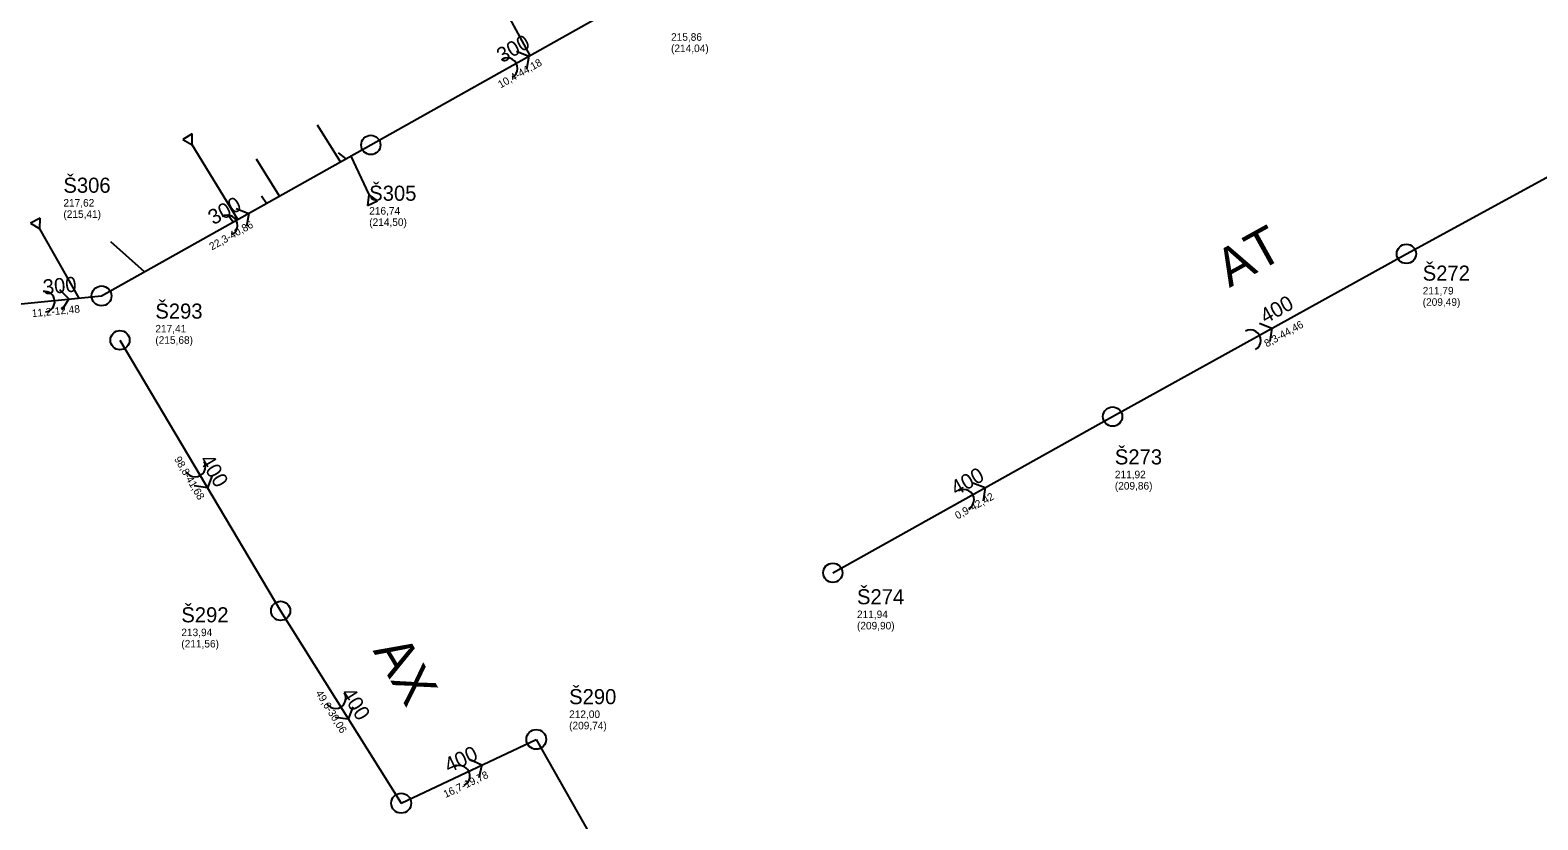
# Model space of a CAD drawing. Extents: x -574467 to -573663, y -1191209 to -1190406.
# Drawn here: x -574172.6 to -573973, y -1190649.1 to -1190544.6 of the extents above; entities that cross this region are included whole.
import ezdxf

# ---------------------------------------------------------------- set-up
doc = ezdxf.new("R2010")
doc.units = 0
for name, color, linetype in [('Vrstva 1', 7, 'Continuous'), ('Vrstva 12', 7, 'Continuous'), ('Vrstva 15', 7, 'Continuous'), ('Vrstva 29', 7, 'Continuous'), ('Vrstva 35', 7, 'Continuous'), ('Vrstva 41', 7, 'Continuous'), ('Vrstva 44', 7, 'Continuous'), ('Vrstva 45', 7, 'Continuous'), ('Vrstva 56', 7, 'Continuous'), ('Vrstva 57', 7, 'Continuous')]:
    doc.layers.add(name, color=color, linetype=linetype)

# ---------------------------------------------------------------- blocks, each defined once
blk = doc.blocks.new('100')
at = {"layer": 'Vrstva 1'}
blk.add_circle((0, 0), 1.27, dxfattribs=at)
blk = doc.blocks.new('106')
at = {"layer": 'Vrstva 1'}
for p, q in [((1.25, 0.72), (0, 0)), ((0, 0), (1.25, -0.72)), ((1.25, -0.72), (1.25, 0.72))]:
    blk.add_line(p, q, dxfattribs=at)
blk = doc.blocks.new('91')
at = {"layer": 'Vrstva 1'}
blk.add_lwpolyline([(0.79, 1.37), (1.89, 0), (0.79, -1.38)], dxfattribs=at)
blk.add_arc((-1.37, 0), 1.37, 270, 90, dxfattribs=at)
blk = doc.blocks.new('86')
at = {"layer": 'Vrstva 1'}
blk.add_lwpolyline([(0.79, 1.37), (1.89, 0), (0.79, -1.38)], dxfattribs=at)
blk.add_arc((-1.37, 0), 1.37, 270, 90, dxfattribs=at)

msp = doc.modelspace()

# ---------------------------------------------------------------- linework, layer by layer
at = {"layer": 'Vrstva 12'}
for p, q in [((-574106.44, -1190547.919), (-574112.039, -1190537.511)), ((-574131.516, -1190562.017), (-574134.55, -1190557.168)), ((-574145.096, -1190569.634), (-574151.152, -1190559.739)), ((-574130.766, -1190561.596), (-574131.785, -1190560.82)), ((-574139.584, -1190566.542), (-574142.65, -1190561.64)), ((-574130.164, -1190561.259), (-574127.779, -1190566.332)), ((-574141.319, -1190567.516), (-574141.976, -1190566.531)), ((-574145.75, -1190570.001), (-574146.416, -1190569.003)), ((-574166.126, -1190580.052), (-574171.298, -1190570.889)), ((-574157.463, -1190576.57), (-574161.921, -1190572.616))]:
    msp.add_line(p, q, dxfattribs=at)
at = {"layer": 'Vrstva 15'}
for p, q in [((-574127.51, -1190559.77), (-574089, -1190538.11)), ((-573990.44, -1190574.19), (-573950.17, -1190552.21)), ((-574163.15, -1190579.76), (-574127.51, -1190559.77)), ((-574029.33, -1190595.74), (-573990.44, -1190574.19)), ((-574175.57, -1190580.98), (-574163.15, -1190579.76)), ((-574160.71, -1190585.62), (-574139.45, -1190621.47)), ((-574066.36, -1190616.43), (-574029.33, -1190595.74)), ((-574139.45, -1190621.47), (-574123.49, -1190646.94)), ((-574123.49, -1190646.94), (-574105.61, -1190638.49)), ((-574105.61, -1190638.49), (-574090.06, -1190666.02))]:
    msp.add_line(p, q, dxfattribs=at)

# ---------------------------------------------------------------- block references
at = {"layer": 'Vrstva 12'}
for p, xscale, yscale, rotation in [((-574151.152, -1190559.739), 0.9999999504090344, 0.9999999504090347, 121.00000158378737), ((-574127.779, -1190566.332), 0.9999999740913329, 0.9999999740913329, -65.99999939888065), ((-574171.298, -1190570.889), 0.999999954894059, 0.9999999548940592, 119.00000058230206)]:
    msp.add_blockref('106', p, dxfattribs=dict(at, xscale=xscale, yscale=yscale, rotation=rotation))
at = {"layer": 'Vrstva 29'}
for p, xscale, yscale, rotation in [((-574127.51, -1190559.77), 1.0072562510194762, 1.0072562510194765, -151.23333635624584), ((-573990.44, -1190574.19), 1.0072562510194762, 1.0072562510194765, -151.23333635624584), ((-574163.15, -1190579.76), 1.0365458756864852, 1.0365458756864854, -158.02850914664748), ((-574160.71, -1190585.62), 0.9999999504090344, 0.9999999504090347, 121.00000158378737), ((-574029.33, -1190595.74), 1.0072562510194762, 1.0072562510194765, -151.23333635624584), ((-574066.36, -1190616.43), 1.0072562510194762, 1.0072562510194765, -151.23333635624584), ((-574139.45, -1190621.47), 0.9999999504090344, 0.9999999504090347, 121.00000158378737), ((-574105.61, -1190638.49), 1.0335064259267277, 1.033506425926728, 156.95871849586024), ((-574123.49, -1190646.94), 1.0365458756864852, 1.0365458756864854, 158.02850914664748)]:
    msp.add_blockref('100', p, dxfattribs=dict(at, xscale=xscale, yscale=yscale, rotation=rotation))
at = {"layer": 'Vrstva 41'}
for name, p, xscale, yscale, rotation in [('91', (-574108.255, -1190548.94), 1.0037041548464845, 1.0037041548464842, 29.379208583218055), ('91', (-574145.33, -1190569.765), 1.0037041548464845, 1.0037041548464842, 29.379208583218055), ('91', (-574169.36, -1190580.37), 1.0011216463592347, 1.0011216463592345, 6.5826102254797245), ('86', (-574009.885, -1190584.965), 1.0037041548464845, 1.0037041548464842, 29.379208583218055), ('86', (-574150.08, -1190603.545), 0.9999999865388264, 0.9999999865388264, -59.99999955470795), ('86', (-574047.845, -1190606.085), 1.0037041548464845, 1.0037041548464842, 29.379208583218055), ('86', (-574131.47, -1190634.205), 0.9999999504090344, 0.9999999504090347, -58.99999841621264), ('86', (-574114.55, -1190642.715), 1.0169561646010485, 1.0169561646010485, 26.97601647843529)]:
    msp.add_blockref(name, p, dxfattribs=dict(at, xscale=xscale, yscale=yscale, rotation=rotation))

# ---------------------------------------------------------------- texts
at = {"layer": 'Vrstva 35'}
for s, rotation, p in [('AT', 28.99, (-574013.868, -1190578.721)), ('AX', 300.67, (-574127.296, -1190626.74))]:
    msp.add_text(s, height=5, rotation=rotation, dxfattribs=at).set_placement(p)
at = {"layer": 'Vrstva 44'}
for s, rotation, p in [('300', 29.36, (-574110.138, -1190548.96)), ('300', 29.29, (-574148.341, -1190570.421)), ('300', 5.61, (-574170.819, -1190579.606)), ('400', 28.99, (-574009.086, -1190583.491)), ('400', 300.67, (-574150.251, -1190601.486)), ('400', 29.19, (-574050.03, -1190606.273)), ('400', 302.07, (-574131.537, -1190632.402)), ('400', 25.3, (-574117.183, -1190642.968))]:
    msp.add_text(s, height=2, rotation=rotation, dxfattribs=at).set_placement(p)
at = {"layer": 'Vrstva 45'}
for s, rotation, p in [('10,4-44,18', 29.36, (-574110.332, -1190552.287)), ('22,3-40,86', 29.29, (-574148.548, -1190573.747)), ('11,2-12,48', 5.61, (-574172.334, -1190582.575)), ('8,3-44,46', 28.99, (-574008.911, -1190586.595)), ('98,8-41,68', 300.67, (-574153.575, -1190601.374)), ('0,9-42,42', 29.19, (-574049.848, -1190609.378)), ('49,6-30,06', 302.07, (-574134.859, -1190632.366)), ('16,7-19,78', 25.3, (-574117.617, -1190646.264))]:
    msp.add_text(s, height=1, rotation=rotation, dxfattribs=at).set_placement(p)
at = {"layer": 'Vrstva 56'}
for s, p in [('215,86 ', (-574087.77, -1190545.97)), ('(214,04)', (-574087.77, -1190547.47)), ('217,62 ', (-574168.2, -1190567.93)), ('(215,41)', (-574168.2, -1190569.43)), ('216,74 ', (-574127.72, -1190568.99)), ('(214,50)', (-574127.72, -1190570.49)), ('211,79 ', (-573988.28, -1190579.57)), ('(209,49)', (-573988.28, -1190581.07)), ('217,41 ', (-574156.03, -1190584.6)), ('(215,68)', (-574156.03, -1190586.1)), ('211,92 ', (-574029.03, -1190603.91)), ('(209,86)', (-574029.03, -1190605.41)), ('211,94 ', (-574063.16, -1190622.43)), ('(209,90)', (-574063.16, -1190623.93)), ('213,94 ', (-574152.59, -1190624.82)), ('(211,56)', (-574152.59, -1190626.32)), ('212,00 ', (-574101.26, -1190635.66)), ('(209,74)', (-574101.26, -1190637.16))]:
    msp.add_text(s, height=1, dxfattribs=at).set_placement(p)
at = {"layer": 'Vrstva 57'}
for s, p in [('Š306', (-574168.2, -1190566.1)), ('Š305', (-574127.72, -1190567.16)), ('Š272', (-573988.28, -1190577.74)), ('Š293', (-574156.03, -1190582.77)), ('Š273', (-574029.03, -1190602.08)), ('Š274', (-574063.16, -1190620.6)), ('Š292', (-574152.59, -1190622.99)), ('Š290', (-574101.26, -1190633.83))]:
    msp.add_text(s, height=2, dxfattribs=at).set_placement(p)

doc.saveas('drawing.dxf')
